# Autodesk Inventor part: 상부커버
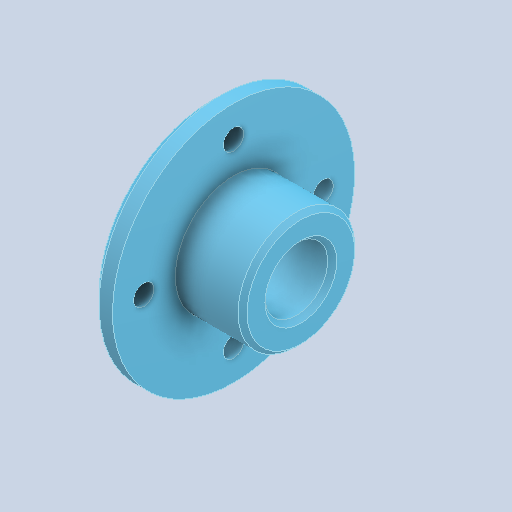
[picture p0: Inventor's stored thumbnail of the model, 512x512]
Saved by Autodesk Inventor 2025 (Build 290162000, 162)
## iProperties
Created: 2024-07
Part Number: 상부커버
Material: 알루미늄 6061
Document SubType Name: Modeling
Designer: anfro
Density: 2.71 g/cm^3
Appearance: 기본값
Author: jhkim
Sending System: Autodesk Inventor 2025
Preprocessor: ST-DEVELOPER v20
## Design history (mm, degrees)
feature "솔리드1"
node "솔리드2"
